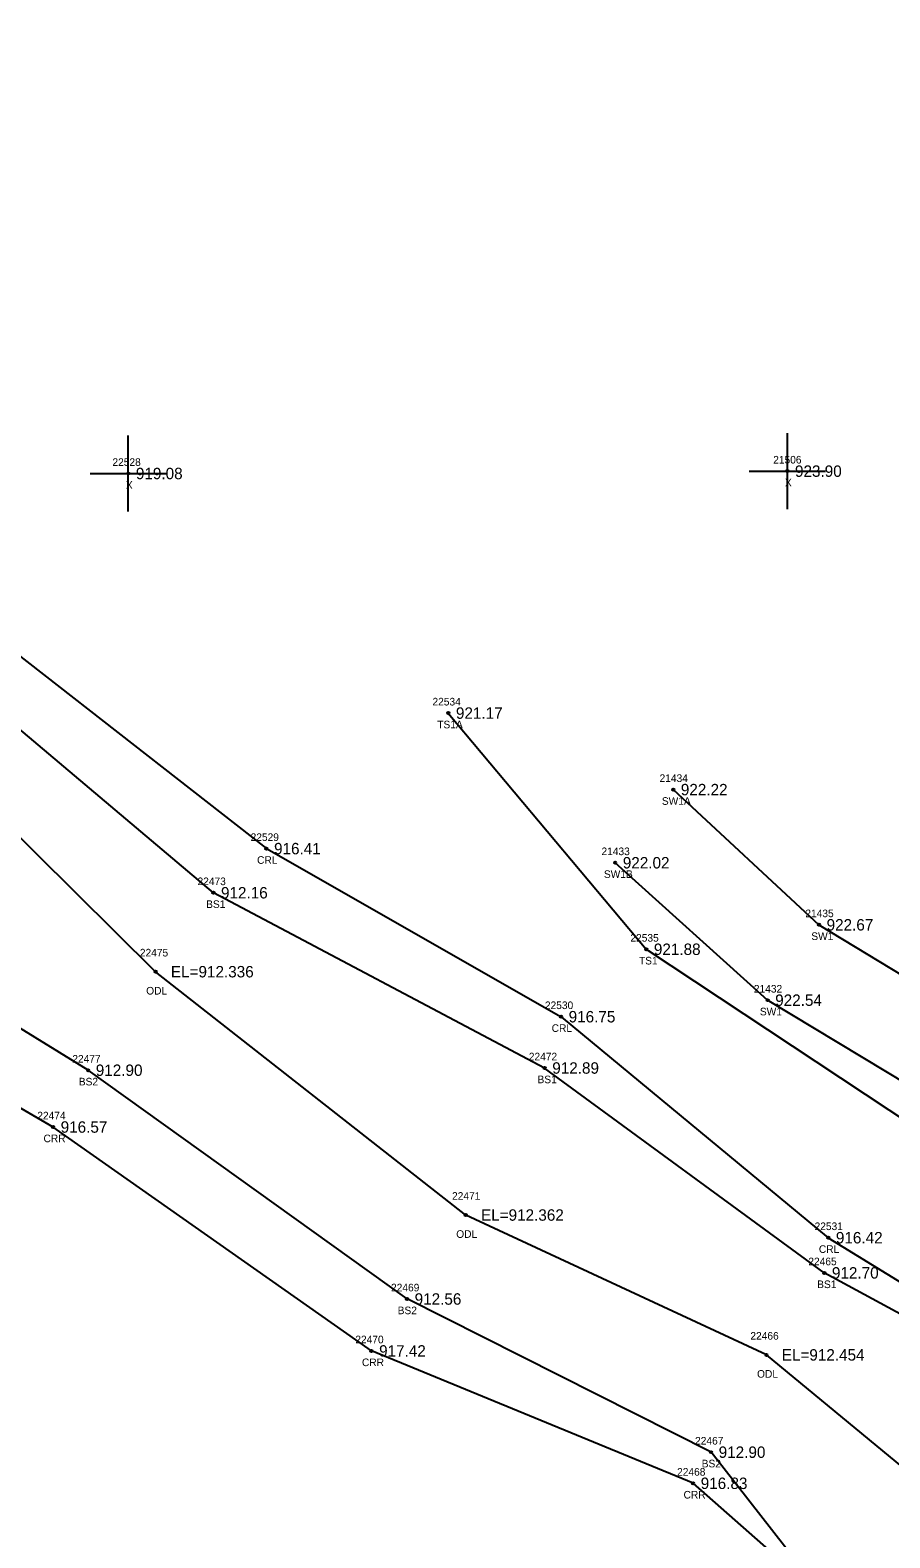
# Model space of a CAD drawing. Extents: x 1576181 to 1577685, y 1099396 to 1101490.
# Drawn here: x 1576753.8 to 1576866.7, y 1100432.1 to 1100630.2 of the extents above; entities that cross this region are included whole.
import ezdxf

# ---------------------------------------------------------------- set-up
doc = ezdxf.new("R2010")
doc.units = 0
for name, color, linetype in [('RD_DTM_BkLn2', 7, 'Continuous'), ('RD_DTM_BkLn_txCode', 7, 'Continuous'), ('RD_EX_Conc', 7, 'Continuous'), ('RD_EX_Conc_txCode', 7, 'Continuous'), ('RD_EX_H2O', 7, 'Continuous'), ('RD_EX_H2O_txCode', 7, 'Continuous'), ('RD_EX_Misc', 7, 'Continuous'), ('RD_EX_Misc_txCode', 7, 'Continuous'), ('RD_EX_TX_Conc_ELEV', 7, 'Continuous'), ('RD_EX_TX_H2O_ELEV', 7, 'Continuous'), ('RD_EX_TX_Misc_ELEV', 7, 'Continuous'), ('RD_SMD_Locator', 7, 'Continuous')]:
    doc.layers.add(name, color=color, linetype=linetype)

msp = doc.modelspace()

# ---------------------------------------------------------------- linework, layer by layer
at = {"layer": 'RD_DTM_BkLn2'}
for points in [[(1576886.42, 1100451.57), (1576858.1, 1100466.95), (1576821.38, 1100493.86), (1576777.88, 1100516.88), (1576744.71, 1100544.83), (1576704.93, 1100574.6), (1576655, 1100608.74), (1576614.63, 1100641.39), (1576576.87, 1100675.44), (1576532.94, 1100708.92), (1576490.23, 1100740.56)], [(1576875.87, 1100417.22), (1576860.46, 1100423.56), (1576856.3, 1100426.66), (1576843.23, 1100443.4), (1576803.31, 1100463.52), (1576761.44, 1100493.57), (1576725.45, 1100515.73), (1576681.3, 1100547.02), (1576635.87, 1100579.97), (1576595.08, 1100610.51), (1576554.15, 1100644.81), (1576510.62, 1100680.61), (1576466.87, 1100717.7)], [(1576808.73, 1100540.48), (1576834.72, 1100509.46), (1576869.79, 1100486.2)]]:
    msp.add_lwpolyline(points, dxfattribs=at)
at = {"layer": 'RD_EX_Conc'}
for points in [[(1576838.26, 1100530.43), (1576857.4, 1100512.67), (1576877.92, 1100500.23)], [(1576906.94, 1100470.82), (1576885.43, 1100482.49), (1576882.08, 1100477.47), (1576870.02, 1100484.29), (1576872.36, 1100489.68), (1576850.65, 1100502.77), (1576830.64, 1100520.82)]]:
    msp.add_lwpolyline(points, dxfattribs=at)
at = {"layer": 'RD_EX_H2O'}
for points in [[(1576494.39, 1100746.79), (1576534.48, 1100716.7), (1576580.85, 1100681.51), (1576619.55, 1100647.19), (1576656.92, 1100617.1), (1576703.9, 1100584.73), (1576745.77, 1100553.17), (1576784.85, 1100522.68), (1576823.53, 1100500.6), (1576858.62, 1100471.57), (1576888.07, 1100453.49), (1576895.55, 1100445.92)], [(1576881.04, 1100430.95), (1576850.51, 1100456.18), (1576811.02, 1100474.55), (1576770.3, 1100506.51), (1576738.8, 1100537.68), (1576691.12, 1100558.51), (1576645.69, 1100592.61), (1576611.01, 1100637.34), (1576572.36, 1100669.07), (1576520.62, 1100693.32), (1576482.36, 1100733.93)], [(1576877.84, 1100413.89), (1576869.37, 1100413.62), (1576860.97, 1100422.67), (1576855.58, 1100426.36), (1576840.87, 1100439.31), (1576798.64, 1100456.7), (1576756.83, 1100486.11), (1576719.94, 1100507.6), (1576677.18, 1100540.85), (1576627.08, 1100575.48), (1576584.18, 1100605.6), (1576548.29, 1100637.23), (1576503.87, 1100673.91), (1576459.55, 1100707.51)]]:
    msp.add_lwpolyline(points, dxfattribs=at)
at = {"layer": 'RD_EX_Misc'}
for p, q in [((1576766.71, 1100566.95), (1576766.71, 1100576.95)), ((1576853.25, 1100567.26), (1576853.25, 1100577.26)), ((1576848.25, 1100572.26), (1576858.25, 1100572.26)), ((1576761.71, 1100571.95), (1576771.71, 1100571.95))]:
    msp.add_line(p, q, dxfattribs=at)
at = {"layer": 'RD_SMD_Locator'}
for centre in [(1576766.71, 1100571.95), (1576853.25, 1100572.26), (1576808.73, 1100540.48), (1576838.26, 1100530.43), (1576784.85, 1100522.68), (1576830.64, 1100520.82), (1576777.88, 1100516.88), (1576857.4, 1100512.67), (1576834.72, 1100509.46), (1576770.3, 1100506.51), (1576850.65, 1100502.77), (1576823.53, 1100500.6), (1576761.44, 1100493.57), (1576821.38, 1100493.86), (1576756.83, 1100486.11), (1576811.02, 1100474.55), (1576858.62, 1100471.57), (1576858.1, 1100466.95), (1576803.31, 1100463.52), (1576798.64, 1100456.7), (1576850.51, 1100456.18), (1576843.23, 1100443.4), (1576840.87, 1100439.31)]:
    msp.add_circle(centre, 0.15, dxfattribs=at)

# ---------------------------------------------------------------- texts
at = {"layer": 'RD_DTM_BkLn_txCode'}
for s, p in [('22534', (1576806.65, 1100541.48)), ('TS1A', (1576807.28, 1100538.48)), ('22473', (1576775.8, 1100517.88)), ('BS1', (1576776.93, 1100514.88)), ('22535', (1576832.64, 1100510.46)), ('TS1', (1576833.76, 1100507.46)), ('22477', (1576759.36, 1100494.57)), ('22472', (1576819.3, 1100494.86)), ('BS1', (1576820.44, 1100491.86)), ('BS2', (1576760.21, 1100491.57)), ('22465', (1576856, 1100467.95)), ('22469', (1576801.21, 1100464.52)), ('BS1', (1576857.16, 1100464.95)), ('BS2', (1576802.08, 1100461.52)), ('22467', (1576841.13, 1100444.4)), ('BS2', (1576842, 1100441.4))]:
    msp.add_text(s, height=1, dxfattribs=at).set_placement(p)
at = {"layer": 'RD_EX_Conc_txCode'}
for s, p in [('21434', (1576836.47, 1100531.43)), ('SW1A', (1576836.77, 1100528.43)), ('21433', (1576828.84, 1100521.82)), ('SW1B', (1576829.16, 1100518.82)), ('21435', (1576855.61, 1100513.67)), ('SW1', (1576856.39, 1100510.67)), ('21432', (1576848.85, 1100503.77)), ('SW1', (1576849.64, 1100500.77))]:
    msp.add_text(s, height=1, dxfattribs=at).set_placement(p)
at = {"layer": 'RD_EX_H2O_txCode'}
for s, p in [('22529', (1576782.77, 1100523.68)), ('CRL', (1576783.62, 1100520.68)), ('22475', (1576768.23, 1100508.51)), ('ODL', (1576769.06, 1100503.51)), ('22530', (1576821.41, 1100501.6)), ('CRL', (1576822.3, 1100498.6)), ('22474', (1576754.76, 1100487.11)), ('CRR', (1576755.58, 1100484.11)), ('22471', (1576809.22, 1100476.55)), ('22531', (1576856.82, 1100472.57)), ('ODL', (1576809.77, 1100471.55)), ('CRL', (1576857.39, 1100469.57)), ('22466', (1576848.39, 1100458.18)), ('22470', (1576796.52, 1100457.7)), ('CRR', (1576797.39, 1100454.7)), ('ODL', (1576849.27, 1100453.18)), ('22468', (1576838.77, 1100440.31)), ('CRR', (1576839.62, 1100437.31))]:
    msp.add_text(s, height=1, dxfattribs=at).set_placement(p)
at = {"layer": 'RD_EX_Misc_txCode'}
for s, p in [('21506', (1576851.39, 1100573.26)), ('22528', (1576764.63, 1100572.95)), ('X', (1576766.39, 1100569.95)), ('X', (1576852.93, 1100570.26))]:
    msp.add_text(s, height=1, dxfattribs=at).set_placement(p)
at = {"layer": 'RD_EX_TX_Conc_ELEV'}
for s, p in [('922.22', (1576839.26, 1100529.68)), ('922.02', (1576831.64, 1100520.07)), ('922.67', (1576858.4, 1100511.92)), ('922.54', (1576851.65, 1100502.02))]:
    msp.add_text(s, height=1.5, dxfattribs=at).set_placement(p)
at = {"layer": 'RD_EX_TX_H2O_ELEV'}
for s, p in [('916.41', (1576785.85, 1100521.93)), ('EL=912.336', (1576772.3, 1100505.76)), ('916.75', (1576824.53, 1100499.85)), ('916.57', (1576757.83, 1100485.36)), ('EL=912.362', (1576813.02, 1100473.8)), ('916.42', (1576859.62, 1100470.82)), ('917.42', (1576799.64, 1100455.95)), ('EL=912.454', (1576852.51, 1100455.43)), ('916.83', (1576841.87, 1100438.56))]:
    msp.add_text(s, height=1.5, dxfattribs=at).set_placement(p)
at = {"layer": 'RD_EX_TX_Misc_ELEV'}
for s, p in [('919.08', (1576767.71, 1100571.2)), ('923.90', (1576854.25, 1100571.51)), ('921.17', (1576809.73, 1100539.73)), ('912.16', (1576778.88, 1100516.13)), ('921.88', (1576835.72, 1100508.71)), ('912.90', (1576762.44, 1100492.82)), ('912.89', (1576822.38, 1100493.11)), ('912.70', (1576859.1, 1100466.2)), ('912.56', (1576804.31, 1100462.77)), ('912.90', (1576844.23, 1100442.65))]:
    msp.add_text(s, height=1.5, dxfattribs=at).set_placement(p)

doc.saveas('drawing.dxf')
